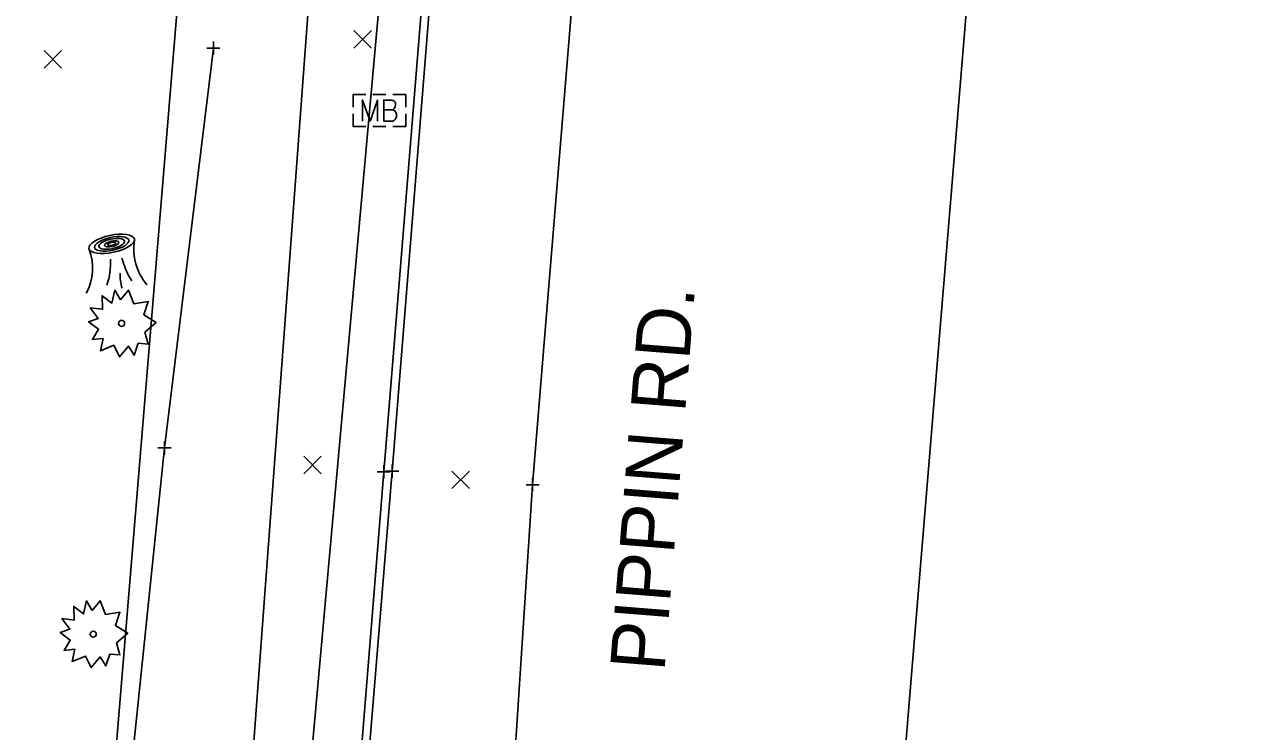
# Model space of a CAD drawing. Extents: x 1380550 to 1381945, y 468927 to 470496.
# Drawn here: x 1381498.4 to 1381592.4, y 469212.5 to 469266.4 of the extents above; entities that cross this region are included whole.
import ezdxf

# ---------------------------------------------------------------- set-up
doc = ezdxf.new("R2010")
doc.units = 0
for name, color, linetype in [('DR_X_Storm_Sewer', 7, 'Continuous'), ('PV_X_COP', 7, 'Continuous'), ('PV_X_Curb', 7, 'Continuous'), ('PV_X_EOP', 7, 'Continuous'), ('RD_X_Cells', 7, 'Continuous'), ('RD_X_Text', 7, 'Continuous'), ('RW_X_Esmt_General', 7, 'Continuous'), ('SV_X_Random_Point', 7, 'Continuous'), ('SV_X_Shot_Marker', 7, 'Continuous'), ('SV_X_Toe_of_Slope', 7, 'Continuous'), ('UT_X_Electric', 7, 'Continuous'), ('UT_X_Telecom', 7, 'Continuous'), ('VG_X_Cells', 7, 'Continuous')]:
    doc.layers.add(name, color=color, linetype=linetype)

msp = doc.modelspace()

# ---------------------------------------------------------------- linework, layer by layer
at = {"layer": 'DR_X_Storm_Sewer'}
msp.add_line((1381528.037, 469296.447), (1381500.707, 468992.415), dxfattribs=at)
at = {"layer": 'PV_X_COP'}
msp.add_lwpolyline([(1381585.986, 469815.579), (1381581.288, 469760.779), (1381580.3, 469747.86), (1381578.724, 469729.445), (1381576.782, 469708.953), (1381575.288, 469689.792), (1381572.756, 469657.561), (1381569.364, 469615.703), (1381565.36, 469567.235), (1381561.161, 469537.516), (1381558.939, 469486.814), (1381555.385, 469442.034), (1381550.974, 469391.016), (1381547.282, 469345.901), (1381541.953, 469289.547), (1381537.187, 469231.269), (1381533.052, 469168.087), (1381530.317, 469133.741), (1381523.968, 469065.081), (1381520.119, 469021.37), (1381518.183, 469001.306)], dxfattribs=at)
at = {"layer": 'PV_X_Curb'}
msp.add_lwpolyline([(1381528.617, 469268.06), (1381528.681, 469267.335), (1381525.826, 469232.259), (1381523.028, 469197.272), (1381522.806, 469196.001)], dxfattribs=at)
at = {"layer": 'PV_X_EOP'}
msp.add_lwpolyline([(1381539.579, 469392.934), (1381538.092, 469374.979), (1381538.028, 469373.756), (1381535.918, 469348.277), (1381535.792, 469347.09), (1381533.908, 469325.42), (1381532.323, 469307.802), (1381531.559, 469305.549), (1381528.189, 469299.903), (1381527.99, 469296.129), (1381530.343, 469292.534), (1381530.803, 469290.753), (1381530.92, 469290.005), (1381529.4, 469268.085), (1381529.296, 469267.435), (1381526.47, 469232.309), (1381523.61, 469197.346), (1381523.606, 469196.129), (1381521.185, 469168.775), (1381520.163, 469156.66)], dxfattribs=at)
at = {"layer": 'RD_X_Cells'}
for p, q in [((1381524.993, 469261.044), (1381525.995, 469261.044)), ((1381525.505, 469259.822), (1381525.505, 469259.822)), ((1381524.993, 469258.6), (1381525.995, 469258.6))]:
    msp.add_line(p, q, dxfattribs=at)
for points in [[(1381523.505, 469260.074), (1381523.505, 469261.044), (1381524.475, 469261.044)], [(1381526.512, 469261.044), (1381527.505, 469261.044), (1381527.505, 469260.074)], [(1381524.209, 469259.022), (1381524.209, 469260.622), (1381524.788, 469259.022), (1381525.342, 469260.622), (1381525.342, 469259.022)], [(1381526.527, 469259.891), (1381526.59, 469259.954), (1381526.628, 469259.992), (1381526.653, 469260.03), (1381526.665, 469260.055), (1381526.69, 469260.105), (1381526.703, 469260.143), (1381526.728, 469260.231), (1381526.728, 469260.269), (1381526.728, 469260.32), (1381526.716, 469260.395), (1381526.69, 469260.458), (1381526.653, 469260.508), (1381526.59, 469260.559), (1381526.539, 469260.584), (1381526.514, 469260.597), (1381526.451, 469260.622), (1381525.834, 469260.622), (1381525.834, 469259.022), (1381526.527, 469259.022), (1381526.615, 469259.072), (1381526.69, 469259.135), (1381526.753, 469259.236), (1381526.791, 469259.349), (1381526.804, 469259.463), (1381526.804, 469259.539), (1381526.779, 469259.614), (1381526.728, 469259.727), (1381526.665, 469259.803), (1381526.527, 469259.891), (1381525.834, 469259.891)], [(1381524.475, 469258.6), (1381523.505, 469258.6), (1381523.505, 469259.57)], [(1381527.505, 469259.57), (1381527.505, 469258.6), (1381526.512, 469258.6)]]:
    msp.add_lwpolyline(points, dxfattribs=at)
at = {"layer": 'RW_X_Esmt_General'}
for points in [[(1381490.401, 469029.464), (1381590.199, 470237.184), (1380558.689, 470277.035)], [(1381783.194, 470213.888), (1381648.776, 470217.487), (1381563.79, 469189.032)]]:
    msp.add_lwpolyline(points, dxfattribs=at)
at = {"layer": 'SV_X_Random_Point'}
for p, q in [((1381523.559, 469264.595), (1381524.893, 469265.93)), ((1381523.559, 469265.93), (1381524.893, 469264.595)), ((1381499.924, 469263.069), (1381501.258, 469264.404)), ((1381499.924, 469264.404), (1381501.258, 469263.069)), ((1381519.728, 469232.108), (1381521.062, 469233.443)), ((1381519.728, 469233.443), (1381521.062, 469232.108)), ((1381531.026, 469230.976), (1381532.36, 469232.31)), ((1381531.026, 469232.31), (1381532.36, 469230.976))]:
    msp.add_line(p, q, dxfattribs=at)
at = {"layer": 'SV_X_Shot_Marker'}
for p, q in [((1381512.334, 469264.598), (1381513.334, 469264.598)), ((1381512.834, 469265.098), (1381512.834, 469264.098)), ((1381512.834, 469264.598), (1381512.834, 469264.598)), ((1381509.111, 469234.577), (1381509.111, 469233.577)), ((1381508.611, 469234.077), (1381509.611, 469234.077)), ((1381509.111, 469234.077), (1381509.111, 469234.077)), ((1381525.826, 469232.759), (1381525.826, 469231.759)), ((1381526.47, 469232.809), (1381526.47, 469231.809)), ((1381525.326, 469232.259), (1381526.326, 469232.259)), ((1381525.826, 469232.259), (1381525.826, 469232.259)), ((1381525.97, 469232.309), (1381526.97, 469232.309)), ((1381526.47, 469232.309), (1381526.47, 469232.309)), ((1381537.187, 469231.769), (1381537.187, 469230.769)), ((1381536.687, 469231.269), (1381537.687, 469231.269)), ((1381537.187, 469231.269), (1381537.187, 469231.269))]:
    msp.add_line(p, q, dxfattribs=at)
at = {"layer": 'SV_X_Toe_of_Slope'}
msp.add_lwpolyline([(1381512.834, 469264.598), (1381509.111, 469234.077), (1381505.616, 469200.413)], dxfattribs=at)
at = {"layer": 'UT_X_Electric'}
msp.add_lwpolyline([(1381665.562, 470247.404), (1381595.795, 470220.833), (1381581.264, 470018.199), (1381571.968, 469887.64), (1381559.775, 469757.408), (1381543.86, 469565.781), (1381529.165, 469390.12), (1381515.279, 469203.101), (1381540.8, 469054.263)], dxfattribs=at)
at = {"layer": 'UT_X_Telecom'}
msp.add_lwpolyline([(1381665.562, 470247.404), (1381595.346, 470217.51), (1381581.264, 470018.199), (1381571.968, 469887.64), (1381559.775, 469757.408), (1381543.86, 469565.781), (1381529.165, 469390.12), (1381515.279, 469203.101), (1381540.8, 469054.263)], dxfattribs=at)
at = {"layer": 'VG_X_Cells'}
msp.add_line((1381505.455, 469248.142), (1381505.455, 469248.142), dxfattribs=at)
for points in [[(1381505.755, 469245.392), (1381506.36, 469246.127), (1381506.775, 469245.074), (1381507.867, 469245.254), (1381507.528, 469244.242), (1381508.473, 469243.647), (1381507.617, 469242.912), (1381507.867, 469241.999), (1381507.113, 469242.067), (1381506.788, 469241.154), (1381506.36, 469241.846), (1381505.682, 469241.029), (1381505.253, 469241.916), (1381504.233, 469241.486), (1381504.425, 469242.427), (1381503.613, 469242.344), (1381504.087, 469243.134), (1381503.318, 469243.702), (1381504.057, 469243.966), (1381503.45, 469244.769), (1381504.382, 469244.659), (1381504.352, 469245.697), (1381505.105, 469245.129), (1381505.312, 469246.114), (1381505.755, 469245.392)], [(1381503.593, 469221.678), (1381504.198, 469222.413), (1381504.613, 469221.36), (1381505.705, 469221.54), (1381505.366, 469220.528), (1381506.311, 469219.933), (1381505.455, 469219.198), (1381505.705, 469218.285), (1381504.951, 469218.353), (1381504.626, 469217.44), (1381504.198, 469218.132), (1381503.52, 469217.315), (1381503.091, 469218.202), (1381502.071, 469217.772), (1381502.263, 469218.713), (1381501.451, 469218.63), (1381501.925, 469219.42), (1381501.156, 469219.988), (1381501.895, 469220.252), (1381501.288, 469221.055), (1381502.22, 469220.945), (1381502.19, 469221.983), (1381502.943, 469221.415), (1381503.15, 469222.4), (1381503.593, 469221.678)]]:
    msp.add_lwpolyline(points, dxfattribs=at)
for centre in [(1381505.839, 469243.583), (1381503.677, 469219.869)]:
    msp.add_circle(centre, 0.23, dxfattribs=at)
for centre, radius, start, end in [((1381511.06, 469249.283), 4.292, 171.41061, 219.91939), ((1381499.623, 469247.796), 4.003, 331.53375, 20.92689), ((1381499.938, 469248.168), 5.053, 340.79377, 3.54808), ((1381511.963, 469250.199), 6.319, 194.9653, 212.12159), ((1381509.36, 469247.342), 3.639, 178.79264, 197.12241)]:
    msp.add_arc(centre, radius, start, end, dxfattribs=at)
for major_axis in [(1.736, 0.375), (1.302, 0.281), (0.976, 0.211), (0.549, 0.119), (0.309, 0.067)]:
    msp.add_ellipse((1381505.08, 469249.653), major_axis=major_axis, ratio=0.36865, dxfattribs=at)

# ---------------------------------------------------------------- texts
at = {"layer": 'RD_X_Text'}
msp.add_text('PIPPIN RD.', height=4.1667, rotation=85.44278, dxfattribs=at).set_placement((1381547.236, 469216.961))

doc.saveas('drawing.dxf')
